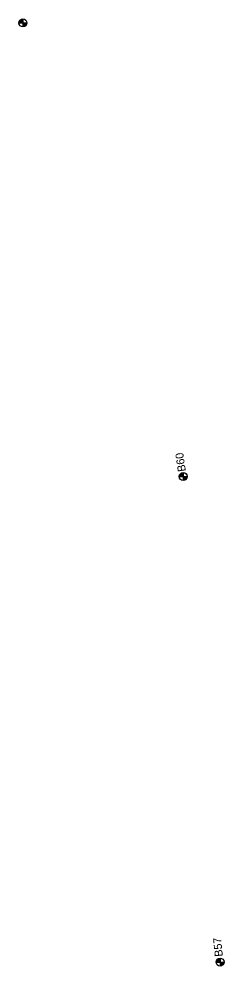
# Model space of a CAD drawing. Extents: x 345549 to 379569, y 127949 to 230467.
# Drawn here: x 359692 to 359949, y 161702 to 162885 of the extents above; entities that cross this region are included whole.
import ezdxf

# ---------------------------------------------------------------- set-up
doc = ezdxf.new("R2010")
doc.units = 0
doc.layers.add('E_SOIL_BORE1 [KAPUR_CADDS_LEVELS]', color=7, linetype='Continuous')
doc.layers.add('P_MARK', color=7, linetype='Continuous')

msp = doc.modelspace()

# ---------------------------------------------------------------- linework, layer by layer
at = {"layer": 'P_MARK'}
for p, q in [((359697, 162884.9), (359697, 162874.9)), ((359692, 162879.9), (359702, 162879.9)), ((359892.4, 162313.3), (359902.4, 162313.3)), ((359897.4, 162318.3), (359897.4, 162308.3)), ((359943.5, 161711.9), (359943.5, 161701.9)), ((359938.5, 161706.9), (359948.5, 161706.9))]:
    msp.add_line(p, q, dxfattribs=at)
for centre in [(359697, 162879.9), (359897.4, 162313.3), (359943.5, 161706.9)]:
    msp.add_circle(centre, 5, dxfattribs=at)
for centre, radius, start, end in [((359697, 162879.9), 4.5, 89.9869, 179.9869), ((359697, 162879.9), 4, 89.9869, 179.9869), ((359697, 162879.9), 3.5, 89.9869, 179.9869), ((359697, 162879.9), 3, 89.9869, 179.9869), ((359697, 162879.9), 2.5, 89.9869, 179.9869), ((359697, 162879.9), 2, 89.9869, 179.9869), ((359697, 162879.9), 1.5, 89.9869, 179.9869), ((359697, 162879.9), 1, 89.9869, 179.9869), ((359697, 162879.9), 0.5, 89.9869, 179.9869), ((359697, 162879.9), 4.5, 269.9869, 359.9869), ((359697, 162879.9), 4, 269.9869, 359.9869), ((359697, 162879.9), 3.5, 269.9869, 359.9869), ((359697, 162879.9), 3, 269.9869, 359.9869), ((359697, 162879.9), 2.5, 269.9869, 359.9869), ((359697, 162879.9), 2, 269.9869, 359.9869), ((359697, 162879.9), 1.5, 269.9869, 359.9869), ((359697, 162879.9), 1, 269.9869, 359.9869), ((359697, 162879.9), 0.5, 269.9869, 359.9869), ((359897.4, 162313.3), 4.5, 89.9869, 179.9869), ((359897.4, 162313.3), 4, 89.9869, 179.9869), ((359897.4, 162313.3), 3.5, 89.9869, 179.9869), ((359897.4, 162313.3), 3, 89.9869, 179.9869), ((359897.4, 162313.3), 2.5, 89.9869, 179.9869), ((359897.4, 162313.3), 2, 89.9869, 179.9869), ((359897.4, 162313.3), 1.5, 89.9869, 179.9869), ((359897.4, 162313.3), 1, 89.9869, 179.9869), ((359897.4, 162313.3), 0.5, 89.9869, 179.9869), ((359897.4, 162313.3), 4.5, 269.9869, 359.9869), ((359897.4, 162313.3), 4, 269.9869, 359.9869), ((359897.4, 162313.3), 3.5, 269.9869, 359.9869), ((359897.4, 162313.3), 3, 269.9869, 359.9869), ((359897.4, 162313.3), 2.5, 269.9869, 359.9869), ((359897.4, 162313.3), 2, 269.9869, 359.9869), ((359897.4, 162313.3), 1.5, 269.9869, 359.9869), ((359897.4, 162313.3), 1, 269.9869, 359.9869), ((359897.4, 162313.3), 0.5, 269.9869, 359.9869), ((359943.5, 161706.9), 4.5, 89.9869, 179.9869), ((359943.5, 161706.9), 4, 89.9869, 179.9869), ((359943.5, 161706.9), 3.5, 89.9869, 179.9869), ((359943.5, 161706.9), 3, 89.9869, 179.9869), ((359943.5, 161706.9), 2.5, 89.9869, 179.9869), ((359943.5, 161706.9), 2, 89.9869, 179.9869), ((359943.5, 161706.9), 1.5, 89.9869, 179.9869), ((359943.5, 161706.9), 1, 89.9869, 179.9869), ((359943.5, 161706.9), 0.5, 89.9869, 179.9869), ((359943.5, 161706.9), 4.5, 269.9869, 359.9869), ((359943.5, 161706.9), 4, 269.9869, 359.9869), ((359943.5, 161706.9), 3.5, 269.9869, 359.9869), ((359943.5, 161706.9), 3, 269.9869, 359.9869), ((359943.5, 161706.9), 2.5, 269.9869, 359.9869), ((359943.5, 161706.9), 2, 269.9869, 359.9869), ((359943.5, 161706.9), 1.5, 269.9869, 359.9869), ((359943.5, 161706.9), 1, 269.9869, 359.9869), ((359943.5, 161706.9), 0.5, 269.9869, 359.9869)]:
    msp.add_arc(centre, radius, start, end, dxfattribs=at)

# ---------------------------------------------------------------- texts
at = {"layer": 'E_SOIL_BORE1 [KAPUR_CADDS_LEVELS]'}
for s, rotation, p in [('B60', 98.5151, (359900.8, 162320.1)), ('B57', 95.5802, (359947, 161714.1))]:
    msp.add_text(s, height=10, rotation=rotation, dxfattribs=at).set_placement(p)

doc.saveas('drawing.dxf')
